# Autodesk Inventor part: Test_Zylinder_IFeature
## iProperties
Created: 2006-07
Part Number: Test_Zylinder_IFeature
Document SubType Name: Modeling
Designer: xxs
Author: xxs
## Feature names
1. Drehung1 [Revolution]
